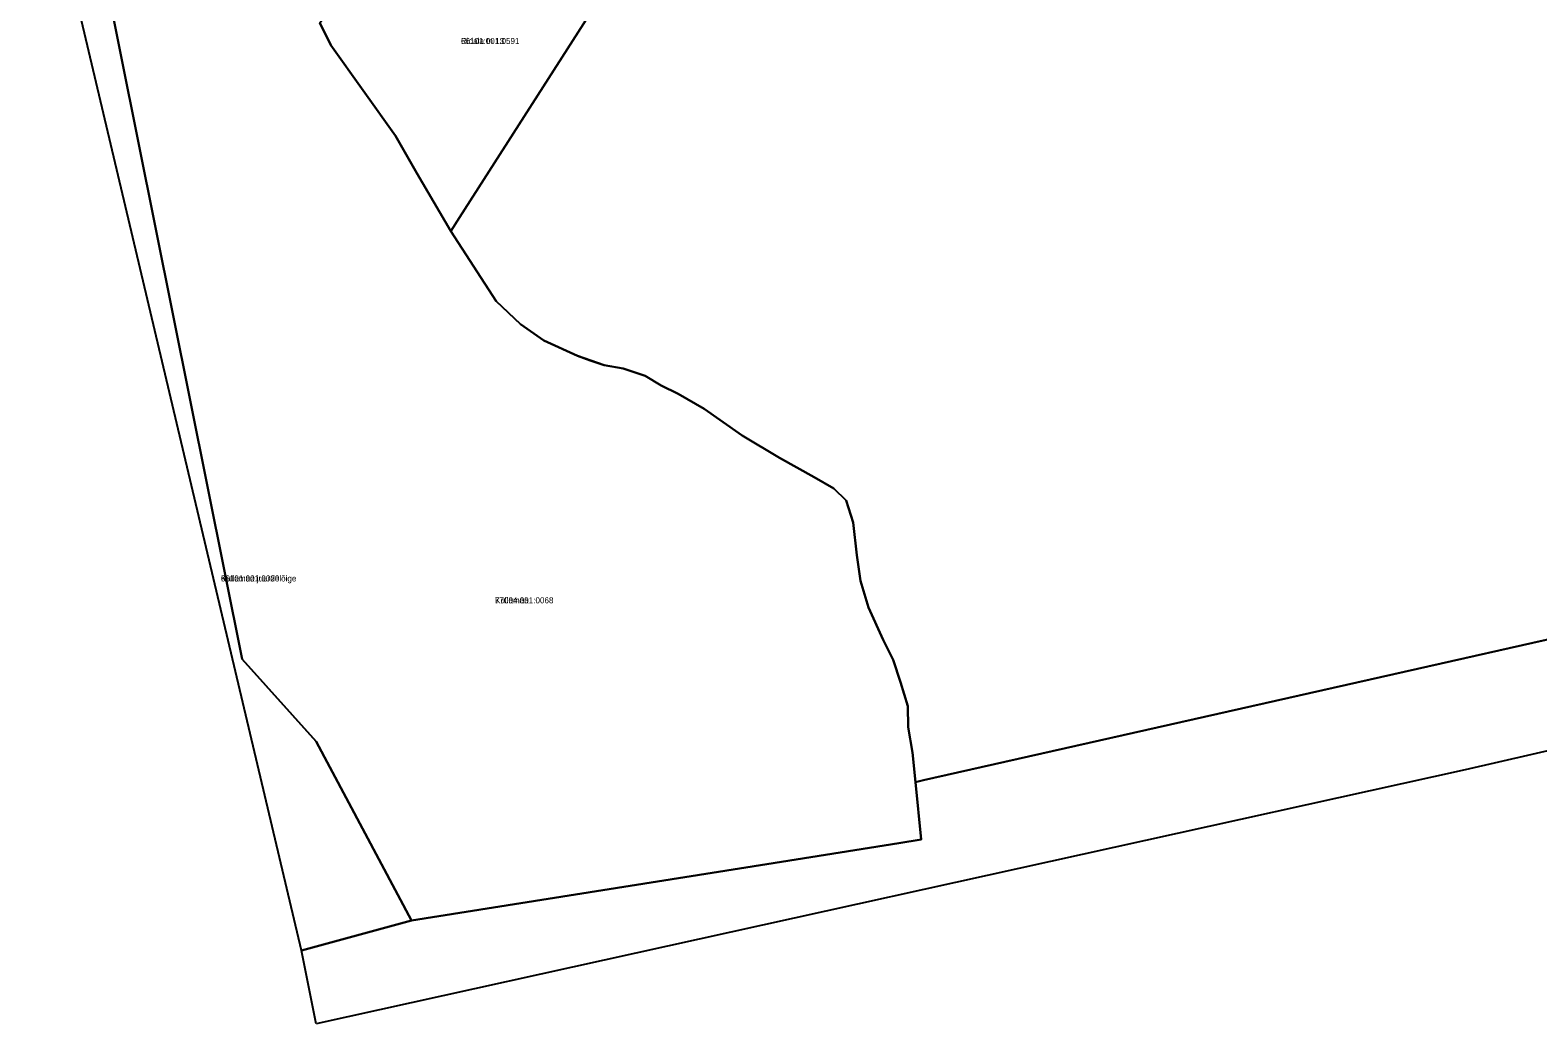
# Model space of a CAD drawing. Extents: x 623860 to 651189, y 6568632 to 6595301.
# Drawn here: x 634904.1 to 635278.1, y 6582521.4 to 6582767.8 of the extents above; entities that cross this region are included whole.
import ezdxf

# ---------------------------------------------------------------- set-up
doc = ezdxf.new("R2010")
doc.units = 0
for name, color, linetype in [('L_AADRESS', 7, 'Continuous'), ('PIIR', 7, 'Continuous'), ('TUNNUS', 7, 'Continuous')]:
    doc.layers.add(name, color=color, linetype=linetype)

msp = doc.modelspace()

# ---------------------------------------------------------------- linework, layer by layer
at = {"layer": 'PIIR'}
for points in [[(634971.4, 6582539.64), (634904.12, 6582824.06), (634913.74, 6582825.94), (634956.72, 6582611.84), (634975.07, 6582591.45), (634998.75, 6582547.01)], [(634979.56, 6582774.16), (635007.84, 6582809.54), (635046.06, 6582776.76), (635010.65, 6582721.3), (635008.49, 6582717.91), (635000, 6582732.32), (634994.72, 6582741.59), (634978.71, 6582764.07), (634975.94, 6582769.62)], [(634975.03, 6582521.43), (634971.4, 6582539.64), (634998.75, 6582547.01), (635086.9, 6582561.03), (635119.64, 6582566.25), (635125.12, 6582567.13), (635123.71, 6582581.36), (635125.7, 6582581.81), (635405.31, 6582644.82), (635585.44, 6582685.42), (635692.92, 6582709.6), (635701.79, 6582676.59), (635694.94, 6582675.59), (635508.89, 6582641.57), (635260.07, 6582584.43)]]:
    msp.add_lwpolyline(points, close=True, dxfattribs=at)
for points in [[(634975.94, 6582769.62), (634978.71, 6582764.07), (634994.72, 6582741.59), (635000, 6582732.32), (635008.49, 6582717.91), (635019.74, 6582700.59), (635025.77, 6582694.92), (635031.52, 6582690.8), (635039.87, 6582687.01), (635043.02, 6582685.91), (635046.55, 6582684.68), (635051.23, 6582683.93), (635056.66, 6582682.08), (635060.62, 6582679.7), (635064.86, 6582677.58), (635071.34, 6582673.88), (635080.74, 6582667.27), (635090, 6582661.72), (635098.6, 6582656.96), (635103.5, 6582654.18), (635106.54, 6582651.14), (635108.26, 6582645.72), (635109.19, 6582637.58), (635110.1, 6582631.29), (635112.05, 6582624.66), (635115.71, 6582616.66), (635118.22, 6582611.63), (635120.05, 6582606.15), (635121.88, 6582600.21), (635121.89, 6582594.95), (635122.99, 6582588.72), (635123.71, 6582581.36), (635125.12, 6582567.13), (635119.64, 6582566.25), (635086.9, 6582561.03), (634998.75, 6582547.01), (634975.07, 6582591.45), (634956.72, 6582611.84), (634913.74, 6582825.94)], [(635405.31, 6582644.82), (635125.7, 6582581.81), (635123.71, 6582581.36), (635122.99, 6582588.72), (635121.89, 6582594.95), (635121.88, 6582600.21), (635120.05, 6582606.15), (635118.22, 6582611.63), (635115.71, 6582616.66), (635112.05, 6582624.66), (635110.1, 6582631.29), (635109.19, 6582637.58), (635108.26, 6582645.72), (635106.54, 6582651.14), (635103.5, 6582654.18), (635098.6, 6582656.96), (635090, 6582661.72), (635080.74, 6582667.27), (635071.34, 6582673.88), (635064.86, 6582677.58), (635060.62, 6582679.7), (635056.66, 6582682.08), (635051.23, 6582683.93), (635046.55, 6582684.68), (635039.87, 6582687.01), (635031.52, 6582690.8), (635025.77, 6582694.92), (635019.74, 6582700.59), (635008.49, 6582717.91), (635010.65, 6582721.3), (635046.06, 6582776.76)]]:
    msp.add_lwpolyline(points, dxfattribs=at)

# ---------------------------------------------------------------- texts
at = {"layer": 'L_AADRESS'}
for s, p in [('Ridala tn 13', (635011, 6582764.34)), ('Kullamaa juurdelõige', (634951.43, 6582631.1)), ('Kullamaa', (635019.43, 6582625.68))]:
    msp.add_text(s, height=1.5, dxfattribs=at).set_placement(p)
at = {"layer": 'TUNNUS'}
for s, p in [('66101:001:0591', (635011, 6582764.34)), ('66101:001:0020', (634951.43, 6582631.1)), ('77004:001:0068', (635019.43, 6582625.68))]:
    msp.add_text(s, height=1.5, dxfattribs=at).set_placement(p)

doc.saveas('drawing.dxf')
